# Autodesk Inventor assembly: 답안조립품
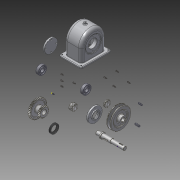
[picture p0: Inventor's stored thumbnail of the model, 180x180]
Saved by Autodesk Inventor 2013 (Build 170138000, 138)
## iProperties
Created: 2016-01
Part Number: 답안조립품
Document SubType Name: Assembly
Designer: Administrator
Author: Administrator
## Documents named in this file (16)
- C:\Documents and Settings\Administrator\바탕 화면\460106v1002\답안조립품.iam
- C:\Documents and Settings\Administrator\바탕 화면\460106v1002\1-본체.ipt
- C:\Documents and Settings\Administrator\바탕 화면\460106v1002\베어링 6203.ipt
- C:\Documents and Settings\Administrator\바탕 화면\460106v1002\뒤커버.ipt
- C:\Documents and Settings\Administrator\바탕 화면\460106v1002\앞커버.ipt
- C:\Documents and Settings\Administrator\바탕 화면\460106v1002\볼트 M3 x 8.ipt
- C:\Documents and Settings\Administrator\바탕 화면\460106v1002\멈춤나사 - M4x10.ipt
- C:\Documents and Settings\Administrator\바탕 화면\460106v1002\볼트 M3 x 10.ipt
- C:\Documents and Settings\Administrator\바탕 화면\460106v1002\부시1.ipt
- C:\Documents and Settings\Administrator\바탕 화면\460106v1002\부시2.ipt
- C:\Documents and Settings\Administrator\바탕 화면\460106v1002\스퍼기어.ipt
- C:\Documents and Settings\Administrator\바탕 화면\460106v1002\오일씰 28 40 8.ipt
- C:\Documents and Settings\Administrator\바탕 화면\460106v1002\축.ipt
- C:\Documents and Settings\Administrator\바탕 화면\460106v1002\키 - 5 x 5 x 18.ipt
- C:\Documents and Settings\Administrator\바탕 화면\460106v1002\키 - 6 x 6 x 22.ipt
- C:\Documents and Settings\Administrator\바탕 화면\460106v1002\V-벨트풀리.ipt
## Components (10 placed, 4 different names)
1. 1-본체:1
2. ISO 4762 M3 x 8:1
3. ISO 4762 M3 x 8:2
4. ISO 4762 M3 x 8:3
5. ISO 4762 M3 x 8:4
6. ISO 4762 M3 x 10:1
7. ISO 4762 M3 x 10:2
8. ISO 4762 M3 x 10:3
9. ISO 4762 M3 x 10:4
10. V-벨트풀리:1
